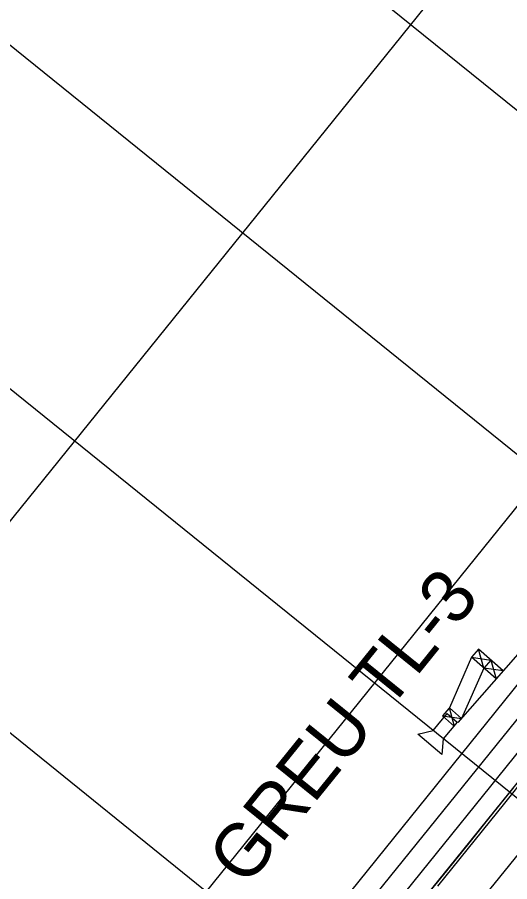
# Model space of a CAD drawing. Extents: x 2293233 to 2294507, y 892788 to 894229.
# Drawn here: x 2293748 to 2293794, y 893375.3 to 893456.1 of the extents above; entities that cross this region are included whole.
import ezdxf

# ---------------------------------------------------------------- set-up
doc = ezdxf.new("R2010")
doc.units = 0
for name, color, linetype in [('COGO Default Curve', 7, 'Continuous'), ('Prop EOT', 7, 'Continuous'), ('Prop Guardrail', 7, 'Continuous'), ('Prop Guardrail Anchor Unit CELL', 7, 'Continuous'), ('Prop Paved Shoulder', 7, 'Continuous'), ('Scratch_Level_4', 7, 'Continuous'), ('Scratch_Level_5', 7, 'Continuous')]:
    doc.layers.add(name, color=color, linetype=linetype)

msp = doc.modelspace()

# ---------------------------------------------------------------- linework, layer by layer
at = {"layer": 'COGO Default Curve'}
msp.add_line((2293758.367, 893332.688), (2294065.501, 893713.269), dxfattribs=at)
for points in [[(2293687.135, 893261.626), (2293692.081, 893266.58), (2293696.991, 893271.57), (2293701.867, 893276.593), (2293706.708, 893281.65), (2293711.514, 893286.74), (2293716.286, 893291.863), (2293721.024, 893297.016), (2293725.728, 893302.2), (2293730.622, 893307.663), (2293735.481, 893313.157), (2293740.305, 893318.68), (2293745.098, 893324.231), (2293750.075, 893330.063), (2293755.02, 893335.922), (2293760.15, 893342.06), (2293765.463, 893348.479), (2293771.172, 893355.436), (2293778.958, 893365), (2293789.02, 893377.439), (2293934.914, 893558.239), (2293982.187, 893616.889)], [(2293795.661, 893385.27), (2293793.568, 893382.676), (2293791.474, 893380.081), (2293789.38, 893377.487), (2293787.287, 893374.893)], [(2293794.415, 893384.124), (2293792.321, 893381.529), (2293790.227, 893378.935), (2293788.133, 893376.341), (2293786.038, 893373.748)]]:
    msp.add_lwpolyline(points, dxfattribs=at)
at = {"layer": 'Prop EOT'}
msp.add_line((2293753.698, 893336.456), (2294060.831, 893717.037), dxfattribs=at)
msp.add_line((2293753.698, 893336.456), (2294060.831, 893717.037), dxfattribs=at)
at = {"layer": 'Prop Guardrail'}
msp.add_spline([(2293791.708, 893335.786), (2293792.121, 893336.32), (2293792.535, 893336.854), (2293792.949, 893337.389), (2293793.363, 893337.923), (2293793.777, 893338.457), (2293794.19, 893338.992), (2293794.604, 893339.526), (2293795.018, 893340.06), (2293795.432, 893340.595), (2293795.846, 893341.129), (2293796.26, 893341.663), (2293796.673, 893342.197), (2293797.087, 893342.732), (2293797.501, 893343.266), (2293797.915, 893343.8), (2293798.329, 893344.335), (2293798.742, 893344.869), (2293799.156, 893345.403), (2293799.57, 893345.938), (2293799.984, 893346.472), (2293800.398, 893347.006), (2293800.812, 893347.54), (2293801.225, 893348.075), (2293801.639, 893348.609), (2293802.053, 893349.143), (2293802.467, 893349.678), (2293802.881, 893350.212), (2293803.294, 893350.746), (2293803.708, 893351.28), (2293804.122, 893351.815), (2293804.536, 893352.349), (2293804.95, 893352.883), (2293805.364, 893353.418), (2293805.777, 893353.952), (2293806.191, 893354.486), (2293806.605, 893355.021), (2293807.019, 893355.555), (2293807.433, 893356.089), (2293807.846, 893356.623), (2293808.26, 893357.158), (2293808.674, 893357.692), (2293809.088, 893358.226), (2293809.502, 893358.761), (2293809.916, 893359.295), (2293810.329, 893359.829), (2293810.743, 893360.364), (2293811.157, 893360.898), (2293811.571, 893361.432), (2293811.985, 893361.966), (2293812.398, 893362.501), (2293812.812, 893363.035), (2293813.226, 893363.569), (2293813.64, 893364.104), (2293814.054, 893364.638), (2293814.468, 893365.172), (2293814.881, 893365.707), (2293815.295, 893366.241), (2293815.709, 893366.775), (2293816.123, 893367.309), (2293816.537, 893367.844), (2293816.951, 893368.378), (2293817.364, 893368.912), (2293817.778, 893369.447), (2293818.192, 893369.981), (2293818.606, 893370.515), (2293819.02, 893371.05), (2293819.433, 893371.584), (2293819.847, 893372.118), (2293820.261, 893372.652), (2293820.675, 893373.187), (2293821.089, 893373.721), (2293821.503, 893374.255), (2293821.916, 893374.79), (2293822.33, 893375.324)], degree=3, dxfattribs=at)
at = {"layer": 'Prop Guardrail Anchor Unit CELL'}
for p, q in [((2293820.006, 893425.388), (2293789.214, 893390.209)), ((2293791.125, 893397.044), (2293790.466, 893396.291)), ((2293793.43, 893395.026), (2293791.125, 893397.044)), ((2293791.618, 893395.282), (2293791.125, 893397.044)), ((2293790.466, 893396.291), (2293788.414, 893391.574)), ((2293792.771, 893394.273), (2293790.466, 893396.291)), ((2293790.466, 893396.291), (2293792.277, 893396.035)), ((2293792.277, 893396.035), (2293791.618, 893395.282)), ((2293792.277, 893396.035), (2293792.771, 893394.273)), ((2293791.618, 893395.282), (2293789.543, 893390.586)), ((2293793.43, 893395.026), (2293791.618, 893395.282)), ((2293788.414, 893391.574), (2293787.756, 893390.821)), ((2293788.414, 893391.574), (2293788.085, 893391.197)), ((2293789.543, 893390.586), (2293788.414, 893391.574)), ((2293788.885, 893389.833), (2293788.414, 893391.574)), ((2293786.883, 893389.459), (2293788.203, 893391.024)), ((2293788.885, 893389.833), (2293787.756, 893390.821)), ((2293787.756, 893390.821), (2293789.543, 893390.586)), ((2293788.203, 893391.024), (2293788.669, 893390.629)), ((2293788.669, 893390.629), (2293789.136, 893390.234)), ((2293789.136, 893390.234), (2293787.816, 893388.67)), ((2293785.468, 893389.111), (2293786.883, 893389.459)), ((2293787.716, 893387.216), (2293785.468, 893389.111)), ((2293787.816, 893388.67), (2293787.716, 893387.216))]:
    msp.add_line(p, q, dxfattribs=at)
at = {"layer": 'Prop Paved Shoulder'}
msp.add_line((2293752.142, 893337.712), (2294059.275, 893718.293), dxfattribs=at)
at = {"layer": 'Scratch_Level_4'}
for p, q in [((2293716.706, 893510.358), (2293950.166, 893321.953)), ((2293701.006, 893490.903), (2293934.466, 893302.498)), ((2293685.306, 893471.448), (2293918.766, 893283.043)), ((2293669.605, 893451.993), (2293903.065, 893263.588))]:
    msp.add_line(p, q, dxfattribs=at)
at = {"layer": 'Scratch_Level_5'}
for p, q in [((2293750.585, 893338.968), (2293936.675, 893569.559)), ((2293790.142, 893462.043), (2293743.041, 893403.678)), ((2293676.842, 893264.332), (2293818.173, 893439.422))]:
    msp.add_line(p, q, dxfattribs=at)

# ---------------------------------------------------------------- texts
at = {"layer": 'Prop Guardrail Anchor Unit CELL'}
msp.add_text('GREU TL-3', height=5, rotation=51.07477, dxfattribs=at).set_placement((2293769.412, 893374.717))

doc.saveas('drawing.dxf')
